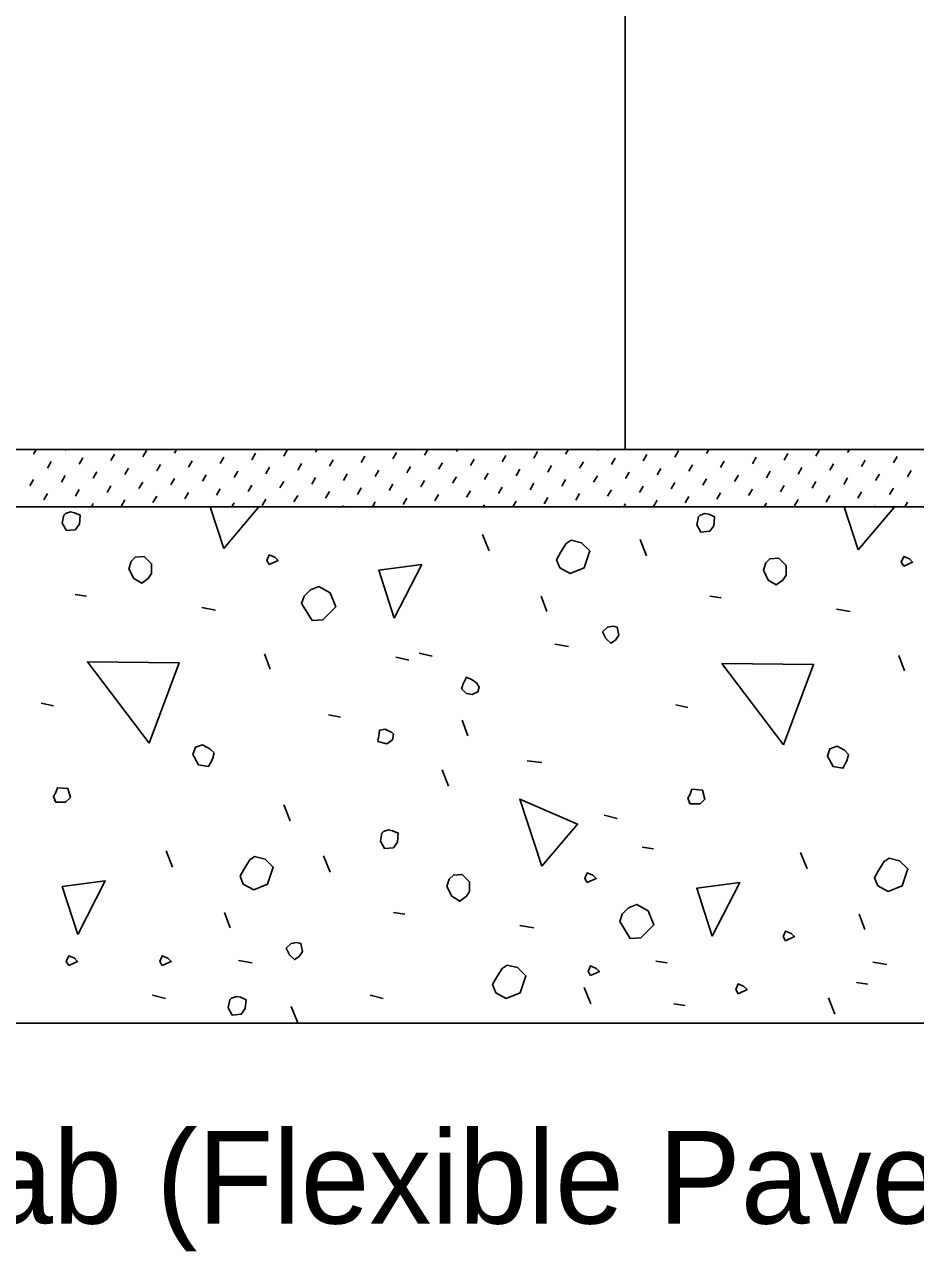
# Model space of a CAD drawing. Extents: x 0 to 41.1, y 0 to 25.9.
# Drawn here: x 4.309 to 6.25, y 9.937 to 12.611 of the extents above; entities that cross this region are included whole.
import ezdxf

# ---------------------------------------------------------------- set-up
doc = ezdxf.new("R2010")
doc.units = 0
for name, color, linetype in [('Dimension', 7, 'Continuous'), ('Miscellaneous', 7, 'Continuous'), ('TrafBarrierConc', 7, 'Continuous')]:
    doc.layers.add(name, color=color, linetype=linetype)

msp = doc.modelspace()

# ---------------------------------------------------------------- linework, layer by layer
at = {"layer": 'Miscellaneous'}
for p, q in [((4.3286, 11.6748), (4.3344, 11.6848)), ((4.3978, 11.6829), (4.3989, 11.6848)), ((4.4283, 11.6524), (4.4364, 11.6664)), ((4.4975, 11.6605), (4.5056, 11.6745)), ((4.5667, 11.6686), (4.5748, 11.6826)), ((4.6358, 11.6767), (4.6405, 11.6848)), ((4.6664, 11.6462), (4.6745, 11.6602)), ((4.7355, 11.6543), (4.7436, 11.6683)), ((4.8047, 11.6624), (4.8128, 11.6764)), ((4.8739, 11.6705), (4.882, 11.6845)), ((4.943, 11.6786), (4.9466, 11.6848)), ((4.9735, 11.6481), (4.9816, 11.6621)), ((5.0427, 11.6562), (5.0508, 11.6702)), ((5.1119, 11.6643), (5.12, 11.6783)), ((5.181, 11.6724), (5.1882, 11.6848)), ((5.2502, 11.6805), (5.2527, 11.6848)), ((5.2807, 11.6499), (5.2888, 11.6639)), ((5.3499, 11.658), (5.358, 11.672)), ((5.4191, 11.6661), (5.4272, 11.6801)), ((5.4882, 11.6742), (5.4943, 11.6848)), ((5.5574, 11.6823), (5.5588, 11.6848)), ((5.5879, 11.6518), (5.596, 11.6658)), ((5.6571, 11.6599), (5.6652, 11.6739)), ((5.7262, 11.668), (5.7343, 11.682)), ((5.7954, 11.6761), (5.8004, 11.6848)), ((5.8259, 11.6456), (5.834, 11.6596)), ((5.8646, 11.6842), (5.8649, 11.6848)), ((5.8951, 11.6537), (5.9032, 11.6677)), ((5.9643, 11.6618), (5.9724, 11.6758)), ((6.0334, 11.6699), (6.0415, 11.6839)), ((6.1026, 11.678), (6.1065, 11.6848)), ((6.1331, 11.6475), (6.1412, 11.6615)), ((6.2023, 11.6556), (6.2104, 11.6696)), ((4.3592, 11.6443), (4.3673, 11.6583)), ((4.4589, 11.6219), (4.467, 11.6359)), ((4.528, 11.63), (4.5361, 11.644)), ((4.5972, 11.6381), (4.6053, 11.6521)), ((4.7661, 11.6238), (4.7742, 11.6378)), ((4.8352, 11.6319), (4.8433, 11.6459)), ((4.9044, 11.64), (4.9125, 11.654)), ((5.0732, 11.6256), (5.0813, 11.6396)), ((5.1424, 11.6337), (5.1505, 11.6477)), ((5.2116, 11.6418), (5.2197, 11.6558)), ((5.3113, 11.6194), (5.3194, 11.6334)), ((5.3804, 11.6275), (5.3885, 11.6415)), ((5.4496, 11.6356), (5.4577, 11.6496)), ((5.5188, 11.6437), (5.5269, 11.6577)), ((5.6184, 11.6213), (5.6266, 11.6353)), ((5.6876, 11.6294), (5.6957, 11.6434)), ((5.7568, 11.6375), (5.7649, 11.6515)), ((5.9256, 11.6232), (5.9337, 11.6372)), ((5.9948, 11.6313), (6.0029, 11.6453)), ((6.064, 11.6394), (6.0721, 11.6534)), ((6.2328, 11.625), (6.2409, 11.639)), ((4.3205, 11.6057), (4.3286, 11.6197)), ((4.3897, 11.6138), (4.3978, 11.6278)), ((4.4894, 11.5913), (4.4975, 11.6053)), ((4.5586, 11.5994), (4.5667, 11.6134)), ((4.6277, 11.6076), (4.6358, 11.6215)), ((4.6969, 11.6157), (4.705, 11.6296)), ((4.7966, 11.5932), (4.8047, 11.6072)), ((4.8657, 11.6013), (4.8739, 11.6153)), ((4.9349, 11.6094), (4.943, 11.6234)), ((5.0041, 11.6175), (5.0122, 11.6315)), ((5.1038, 11.5951), (5.1119, 11.6091)), ((5.1729, 11.6032), (5.181, 11.6172)), ((5.2421, 11.6113), (5.2502, 11.6253)), ((5.411, 11.597), (5.4191, 11.611)), ((5.4801, 11.6051), (5.4882, 11.6191)), ((5.5493, 11.6132), (5.5574, 11.6272)), ((5.7181, 11.5989), (5.7262, 11.6129)), ((5.7873, 11.607), (5.7954, 11.621)), ((5.8565, 11.6151), (5.8646, 11.6291)), ((5.9562, 11.5926), (5.9643, 11.6066)), ((6.0253, 11.6007), (6.0334, 11.6147)), ((6.0945, 11.6088), (6.1026, 11.6228)), ((6.1637, 11.6169), (6.1718, 11.6309)), ((4.3511, 11.5751), (4.3592, 11.5891)), ((4.4202, 11.5832), (4.4283, 11.5972)), ((4.5891, 11.5689), (4.5972, 11.5829)), ((4.6583, 11.577), (4.6664, 11.591)), ((4.7274, 11.5851), (4.7355, 11.5991)), ((4.8963, 11.5708), (4.9044, 11.5848)), ((4.9654, 11.5789), (4.9735, 11.5929)), ((5.0346, 11.587), (5.0427, 11.601)), ((5.1343, 11.5646), (5.1424, 11.5786)), ((5.2035, 11.5727), (5.2116, 11.5867)), ((5.2726, 11.5808), (5.2807, 11.5948)), ((5.3418, 11.5889), (5.3499, 11.6029)), ((5.4415, 11.5665), (5.4496, 11.5804)), ((5.5107, 11.5746), (5.5188, 11.5885)), ((5.5798, 11.5827), (5.5879, 11.5966)), ((5.649, 11.5908), (5.6571, 11.6048)), ((5.7487, 11.5683), (5.7568, 11.5823)), ((5.8178, 11.5764), (5.8259, 11.5904)), ((5.887, 11.5845), (5.8951, 11.5985)), ((6.0559, 11.5702), (6.064, 11.5842)), ((6.125, 11.5783), (6.1331, 11.5923)), ((6.1942, 11.5864), (6.2023, 11.6004)), ((4.4549, 11.5598), (4.4589, 11.5667)), ((4.5199, 11.5608), (4.528, 11.5748)), ((4.6965, 11.5598), (4.6969, 11.5605)), ((4.761, 11.5598), (4.7661, 11.5686)), ((4.8271, 11.5627), (4.8352, 11.5767)), ((5.0026, 11.5598), (5.0041, 11.5624)), ((5.0671, 11.5598), (5.0732, 11.5705)), ((5.3087, 11.5598), (5.3113, 11.5642)), ((5.3732, 11.5598), (5.3804, 11.5723)), ((5.6148, 11.5598), (5.6184, 11.5661)), ((5.6795, 11.5602), (5.6876, 11.5742)), ((5.8564, 11.5598), (5.8565, 11.5599)), ((5.9209, 11.5598), (5.9256, 11.568)), ((5.9867, 11.5621), (5.9948, 11.5761)), ((6.1625, 11.5598), (6.1637, 11.5618)), ((6.227, 11.5598), (6.2328, 11.5699)), ((5.3215, 11.4639), (5.3073, 11.4993)), ((5.6644, 11.4533), (5.6503, 11.4887)), ((4.4199, 11.3685), (4.4446, 11.3649)), ((5.447, 11.3313), (5.4346, 11.3649)), ((5.8023, 11.3649), (5.827, 11.3614)), ((4.6957, 11.3402), (4.7257, 11.3349)), ((6.0781, 11.3366), (6.1081, 11.3313)), ((5.4646, 11.2606), (5.4947, 11.2553)), ((4.8442, 11.2058), (4.8318, 11.2394)), ((5.1182, 11.2324), (5.1465, 11.2253)), ((5.1694, 11.2412), (5.1977, 11.2341)), ((6.2266, 11.2023), (6.2142, 11.2359)), ((4.3457, 11.1316), (4.3722, 11.1263)), ((5.728, 11.1281), (5.7546, 11.1227)), ((4.9714, 11.1068), (4.998, 11.1015)), ((5.2755, 11.0609), (5.2631, 11.0945)), ((5.4045, 11.0061), (5.4364, 11.0025)), ((5.2331, 10.9513), (5.2189, 10.9866)), ((4.8884, 10.8753), (4.8742, 10.9106)), ((5.5725, 10.8876), (5.6008, 10.8806)), ((4.632, 10.7745), (4.6179, 10.8099)), ((5.6553, 10.8177), (5.68, 10.8142)), ((6.0144, 10.771), (6.0003, 10.8063)), ((4.975, 10.7639), (4.9608, 10.7992)), ((4.7575, 10.6419), (4.7452, 10.6755)), ((5.1129, 10.6755), (5.1376, 10.672)), ((6.1399, 10.6384), (6.1276, 10.672)), ((5.3886, 10.6472), (5.4187, 10.6419)), ((4.7752, 10.5712), (4.8053, 10.5659)), ((5.6847, 10.5697), (5.7095, 10.5662)), ((6.1576, 10.5677), (6.1877, 10.5624)), ((5.5429, 10.4768), (5.5288, 10.5122)), ((6.1218, 10.523), (6.1466, 10.5195)), ((4.5883, 10.4953), (4.6166, 10.4883)), ((5.0622, 10.4953), (5.0905, 10.4883)), ((6.0749, 10.4543), (6.0608, 10.4896)), ((4.9045, 10.4351), (4.8903, 10.4705)), ((5.724, 10.4764), (5.7488, 10.4729))]:
    msp.add_line(p, q, dxfattribs=at)
for points in [[(4.7434, 11.4692), (4.7139, 11.5598)], [(4.82, 11.5598), (4.7434, 11.4692)], [(6.1258, 11.4657), (6.0952, 11.5598)], [(6.1986, 11.5598), (6.2036, 11.5576), (6.1258, 11.4657)], [(4.3916, 11.524), (4.4005, 11.5081), (4.4199, 11.5099), (4.4287, 11.5223), (4.4305, 11.5417), (4.4181, 11.547), (4.4093, 11.5488), (4.3987, 11.5452), (4.3951, 11.5417), (4.3916, 11.524)], [(5.774, 11.5205), (5.7828, 11.5046), (5.8023, 11.5064), (5.8111, 11.5187), (5.8129, 11.5382), (5.8005, 11.5435), (5.7917, 11.5452), (5.7811, 11.5417), (5.7775, 11.5382), (5.774, 11.5205)], [(5.4753, 11.4268), (5.4982, 11.4144), (5.5283, 11.4268), (5.5407, 11.4639), (5.523, 11.4816), (5.5, 11.4869), (5.4894, 11.4798), (5.477, 11.4604), (5.4682, 11.4445), (5.4753, 11.4268)], [(4.5366, 11.425), (4.5472, 11.4038), (4.5649, 11.3932), (4.579, 11.4038), (4.5861, 11.4144), (4.5861, 11.4356), (4.5702, 11.4516), (4.5507, 11.4498), (4.5419, 11.4409), (4.5366, 11.425)], [(4.8424, 11.4339), (4.8618, 11.4427), (4.8548, 11.4498), (4.8424, 11.4551), (4.8371, 11.4427), (4.8424, 11.4339)], [(5.919, 11.4215), (5.9296, 11.4003), (5.9472, 11.3897), (5.9614, 11.4003), (5.9685, 11.4109), (5.9685, 11.4321), (5.9526, 11.448), (5.9331, 11.4463), (5.9243, 11.4374), (5.919, 11.4215)], [(6.2248, 11.4303), (6.2442, 11.4392), (6.2372, 11.4463), (6.2248, 11.4516), (6.2195, 11.4392), (6.2248, 11.4303)], [(5.1146, 11.3172), (5.081, 11.4215), (5.1747, 11.4339), (5.1146, 11.3172)], [(4.9131, 11.349), (4.9361, 11.3119), (4.9591, 11.3137), (4.9679, 11.3225), (4.9874, 11.342), (4.975, 11.372), (4.9502, 11.3861), (4.9326, 11.3791), (4.9184, 11.3649), (4.9131, 11.349)], [(5.576, 11.273), (5.5866, 11.2624), (5.5972, 11.2695), (5.6043, 11.2801), (5.6008, 11.2978), (5.5919, 11.2995), (5.5796, 11.2978), (5.5689, 11.2872), (5.576, 11.273)], [(4.5808, 11.045), (4.4464, 11.2217), (4.6462, 11.22), (4.5808, 11.045)], [(5.9632, 11.0414), (5.8288, 11.2182), (6.0286, 11.2164), (5.9632, 11.0414)], [(5.272, 11.1528), (5.2843, 11.151), (5.2967, 11.1563), (5.3002, 11.1669), (5.2949, 11.1758), (5.2843, 11.1829), (5.272, 11.1882), (5.2649, 11.174), (5.2614, 11.1634), (5.272, 11.1528)], [(5.0793, 11.0485), (5.0987, 11.0432), (5.1111, 11.052), (5.1129, 11.0644), (5.1093, 11.0679), (5.0952, 11.075), (5.0828, 11.0733), (5.081, 11.0609), (5.0793, 11.0485)], [(4.6798, 11.0131), (4.6886, 10.9972), (4.7098, 10.9937), (4.7187, 11.0096), (4.7222, 11.0238), (4.7133, 11.0326), (4.6974, 11.0414), (4.6815, 11.0361), (4.6762, 11.0202), (4.6798, 11.0131)], [(6.0622, 11.0096), (6.071, 10.9937), (6.0922, 10.9902), (6.101, 11.0061), (6.1046, 11.0202), (6.0957, 11.0291), (6.0798, 11.0379), (6.0639, 11.0326), (6.0586, 11.0167), (6.0622, 11.0096)], [(4.3775, 10.9159), (4.3987, 10.9159), (4.4093, 10.9265), (4.404, 10.946), (4.381, 10.9477), (4.3775, 10.9371), (4.3722, 10.9283), (4.3775, 10.9159), (4.3739, 10.9195)], [(5.7599, 10.9124), (5.7811, 10.9124), (5.7917, 10.923), (5.7864, 10.9424), (5.7634, 10.9442), (5.7599, 10.9336), (5.7546, 10.9248), (5.7599, 10.9124), (5.7563, 10.9159)], [(5.4364, 10.7763), (5.3886, 10.923), (5.5141, 10.8682), (5.4364, 10.7763)], [(5.0846, 10.8311), (5.0934, 10.8152), (5.1129, 10.8169), (5.1217, 10.8293), (5.1235, 10.8487), (5.1111, 10.854), (5.1023, 10.8558), (5.0916, 10.8523), (5.0881, 10.8487), (5.0846, 10.8311)], [(4.7858, 10.7374), (4.8088, 10.725), (4.8389, 10.7374), (4.8512, 10.7745), (4.8336, 10.7922), (4.8106, 10.7975), (4.8, 10.7904), (4.7876, 10.771), (4.7788, 10.7551), (4.7858, 10.7374)], [(6.1682, 10.7338), (6.1912, 10.7215), (6.2213, 10.7338), (6.2336, 10.771), (6.2159, 10.7886), (6.193, 10.7939), (6.1824, 10.7869), (6.17, 10.7674), (6.1611, 10.7515), (6.1682, 10.7338)], [(5.2295, 10.7321), (5.2401, 10.7109), (5.2578, 10.7003), (5.272, 10.7109), (5.279, 10.7215), (5.279, 10.7427), (5.2631, 10.7586), (5.2437, 10.7568), (5.2348, 10.748), (5.2295, 10.7321)], [(5.5354, 10.7409), (5.5548, 10.7498), (5.5477, 10.7568), (5.5354, 10.7621), (5.5301, 10.7498), (5.5354, 10.7409)], [(4.4252, 10.6278), (4.3916, 10.7321), (4.4853, 10.7444), (4.4252, 10.6278)], [(5.8076, 10.6242), (5.774, 10.7285), (5.8677, 10.7409), (5.8076, 10.6242)], [(5.6061, 10.6561), (5.6291, 10.6189), (5.652, 10.6207), (5.6609, 10.6295), (5.6803, 10.649), (5.6679, 10.679), (5.6432, 10.6932), (5.6255, 10.6861), (5.6114, 10.672), (5.6061, 10.6561)], [(5.9672, 10.6141), (5.9867, 10.623), (5.9796, 10.63), (5.9672, 10.6353), (5.9619, 10.623), (5.9672, 10.6141)], [(4.8866, 10.5836), (4.8972, 10.573), (4.9078, 10.58), (4.9149, 10.5907), (4.9113, 10.6083), (4.9025, 10.6101), (4.8901, 10.6083), (4.8795, 10.5977), (4.8866, 10.5836)], [(4.4056, 10.5601), (4.425, 10.5689), (4.4179, 10.576), (4.4056, 10.5813), (4.4003, 10.5689), (4.4056, 10.5601)], [(4.6094, 10.5601), (4.6288, 10.5689), (4.6217, 10.576), (4.6094, 10.5813), (4.6041, 10.5689), (4.6094, 10.5601)], [(5.336, 10.5007), (5.359, 10.4884), (5.389, 10.5007), (5.4014, 10.5379), (5.3837, 10.5555), (5.3607, 10.5608), (5.3501, 10.5538), (5.3378, 10.5343), (5.3289, 10.5184), (5.336, 10.5007)], [(5.5424, 10.538), (5.5619, 10.5468), (5.5548, 10.5539), (5.5424, 10.5592), (5.5371, 10.5468), (5.5424, 10.538)], [(5.8641, 10.4987), (5.8835, 10.5076), (5.8765, 10.5146), (5.8641, 10.5199), (5.8588, 10.5076), (5.8641, 10.4987)], [(4.7531, 10.4679), (4.7619, 10.452), (4.7814, 10.4538), (4.7902, 10.4662), (4.792, 10.4856), (4.7796, 10.4909), (4.7708, 10.4927), (4.7602, 10.4892), (4.7566, 10.4856), (4.7531, 10.4679)]]:
    msp.add_lwpolyline(points, dxfattribs=at)
at = {"layer": 'TrafBarrierConc'}
for p, q in [((5.6177, 15.1849), (5.6177, 11.6848)), ((0.6166, 11.6848), (8.148, 11.6848)), ((0.6167, 11.5598), (8.148, 11.5598)), ((0.6167, 10.4348), (8.148, 10.4348))]:
    msp.add_line(p, q, dxfattribs=at)

# ---------------------------------------------------------------- texts
at = {"layer": 'Dimension'}
msp.add_text('Approach Slab (Flexible Pavement Approach Slab ', height=0.2016, dxfattribs=at).set_placement((2.7531, 9.9977))

doc.saveas('drawing.dxf')
